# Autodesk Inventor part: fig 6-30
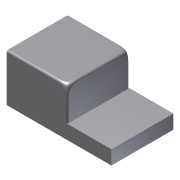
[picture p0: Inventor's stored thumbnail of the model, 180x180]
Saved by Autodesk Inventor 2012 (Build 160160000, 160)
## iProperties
Created: 2004-05
Part Number: fig 6-30
Document SubType Name: Modeling
Designer: CADCIM Technologies
Manufacturer: Standard
Standards Organization: Custom
Density: 1 g/cm^3
Material: Default
Author: CADCIM Technologies
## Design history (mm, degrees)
node "Sketch1"
sketch "Sketch2"
  geometry: L1 (0.098, 47.711)-(0.098, 0.049); L2 (0.098, 0.049)-(-105.483, 0.049); L3 (-105.483, 0.049)-(-105.483, 14.192); L4 (-105.483, 14.192)-(-61.139, 14.192); L5 (-61.139, 14.192)-(-61.139, 47.711); L6 (-61.139, 47.711)-(0.098, 47.711)
  constraints: 12 end point, 3 parallel, 2 perpendicular, 1 vertical
extrude "Extrusion1" new body sketch "Sketch2" stored distance "d0" = 62.5; taper "d1" = 0 deg
fillet "Fillet6" dims "d43" = 10, "d44" = 10, "d45" = 10, "d46" = 10, "d47" = 10, "d48" = 10, "d49" = 2
body "Solid1"
